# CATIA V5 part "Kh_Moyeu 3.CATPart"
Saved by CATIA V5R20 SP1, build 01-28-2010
Part number: Moyeu 3
Bounding box of the stored display mesh (mm): x -31.991 to 31.991, y -32 to 32, z -27 to 27
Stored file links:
  G:\Khaled_CFAO_2011\SIL\SIL_GR1\tmerino\Khaled\CAD_Thinkmotion\Kh_Moyeu 3.CATPart
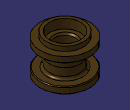
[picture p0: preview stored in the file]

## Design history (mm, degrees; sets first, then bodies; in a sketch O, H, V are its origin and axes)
Body1 (main body)
  Sketch1 on yz-plane, origin (0, 0, 0), H (0, 1, 0), V (0, 0, 1)
    line L1 (13, 0) -> (13, 15)
    point P1 (13, 0)
    point P2 (13, 15)
    line L2 (13, 15) -> (20, 15)
    point P3 (20, 15)
    line L3 (20, 15) -> (20, 27)
    point P4 (20, 27)
    line L4 (20, 27) -> (24, 27)
    point P5 (24, 27)
    line L5 (24, 27) -> (24, 21)
    point P6 (24, 21)
    line L6 (24, 21) -> (32, 21)
    point P7 (32, 21)
    line L7 (32, 21) -> (32, 13)
    point P8 (32, 13)
    line L8 (32, 13) -> (20, 13)
    point P9 (20, 13)
    line L9 (20, 13) -> (20, 0)
    point P10 (20, 0)
    point P11 (13, 0)
    point P12 (13, -15)
    point P13 (20, -15)
    point P14 (20, -27)
    point P15 (24, -27)
    point P16 (24, -21)
    point P17 (32, -21)
    point P18 (32, -13)
    point P19 (20, -13)
    point P20 (20, 0)
    line L10 (13, 0) -> (13, -15)
    line L11 (13, -15) -> (20, -15)
    line L12 (20, -15) -> (20, -27)
    line L13 (20, -27) -> (24, -27)
    line L14 (24, -27) -> (24, -21)
    line L15 (24, -21) -> (32, -21)
    line L16 (32, -21) -> (32, -13)
    line L17 (32, -13) -> (20, -13)
    line L18 (20, -13) -> (20, 0)
    distance L1 V = 13
    length L1 = 15
    distance L3 V = 20
    length L3 = 12
    length L4 = 4
    length L5 = 6
    length L6 = 8
    length L7 = 8
    length L8 = 12
    vertical: L1 V, L3 V, L5 V, L7 V, L9 V
    horizontal: L2 H, L4 H, L6 H, L8 H
    coincidence: P10 H, P1 P11, P10 P20
    symmetry: P1 P11 H, P2 P12 H, P3 P13 H, P4 P14 H, P5 P15 H, P6 P16 H, P7 P17 H, P8 P18 H, P9 P19 H, P10 P20 H, L1 L10 H, L2 L11 H, L3 L12 H, L4 L13 H, L5 L14 H, L6 L15 H, L7 L16 H, L8 L17 H, L9 L18 H
  Shaft1: profile Sketch1, axis Sketch1.V, angle 360
  Fillet1: radius 3, on edge [face of Shaft1 from Sketch1.L17 | face of Shaft1 from Sketch1.L18]; edge [face of Shaft1 from Sketch1.L9 | face of Shaft1 from Sketch1.L8]
  Chamfer1: length 2, angle 45, on edge [face of Shaft1 from Sketch1.L2 | face of Shaft1 from Sketch1.L1]; edge [face of Shaft1 from Sketch1.L10 | face of Shaft1 from Sketch1.L11]
  Chamfer2: length 1, angle 45, on edge [face of Shaft1 from Sketch1.L16 | face of Shaft1 from Sketch1.L17]; edge [face of Shaft1 from Sketch1.L8 | face of Shaft1 from Sketch1.L7]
